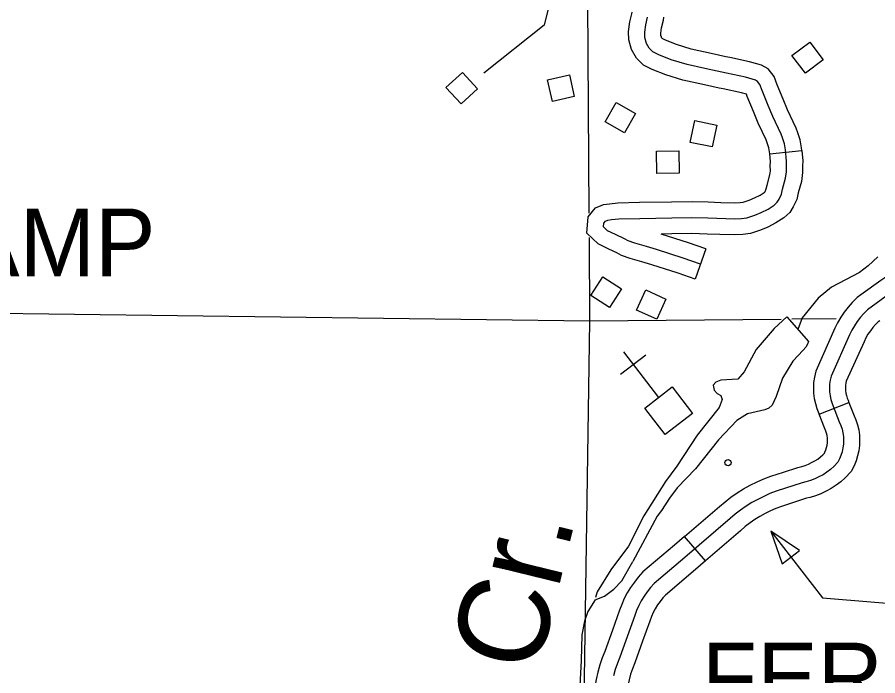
# Model space of a CAD drawing. Extents: x -19 to 366, y -4 to 359.
# Drawn here: x 137.894 to 138.656, y 192.696 to 193.279 of the extents above; entities that cross this region are included whole.
import ezdxf

# ---------------------------------------------------------------- set-up
doc = ezdxf.new("R2010")
doc.units = 0
for name, color, linetype in [('21', 7, 'Continuous'), ('60', 7, 'Continuous'), ('R_Axis Annot', 7, 'Continuous'), ('R_ROW', 7, 'Continuous'), ('R_Temp Easement', 7, 'Continuous'), ('Sheet Fence', 7, 'Continuous')]:
    doc.layers.add(name, color=color, linetype=linetype)

msp = doc.modelspace()

# ---------------------------------------------------------------- linework, layer by layer
at = {"layer": '21'}
msp.add_lwpolyline([(138.37332, 193.32549), (138.36042, 193.27203), (138.307, 193.22963)], dxfattribs=at)
for points in [[(138.60746, 193.24136), (138.59174, 193.22946), (138.57981, 193.24523), (138.59553, 193.25712)], [(138.2879, 193.23022), (138.30129, 193.21576), (138.28679, 193.20232), (138.27339, 193.21678)], [(138.36772, 193.20438), (138.36338, 193.22361), (138.38267, 193.22797), (138.38701, 193.20874)], [(138.43153, 193.17659), (138.41438, 193.18632), (138.42414, 193.20352), (138.44129, 193.19379)], [(138.48979, 193.16816), (138.49379, 193.18746), (138.51315, 193.18346), (138.50915, 193.16415)], [(138.46019, 193.14072), (138.45984, 193.16043), (138.47961, 193.16078), (138.47996, 193.14107)], [(138.41818, 193.02194), (138.4016, 193.0326), (138.4123, 193.04923), (138.42888, 193.03857)], [(138.46822, 193.02935), (138.46, 193.01144), (138.44203, 193.01969), (138.45026, 193.0376)]]:
    msp.add_lwpolyline(points, close=True, dxfattribs=at)
at = {"layer": '60'}
for p, q in [((138.43052, 192.98267), (138.46159, 192.94223)), ((138.42791, 192.96275), (138.45044, 192.98006))]:
    msp.add_line(p, q, dxfattribs=at)
for points in [[(138.5752, 193.01354), (138.59446, 192.99167)], [(138.56115, 192.82369), (138.60671, 192.76481), (138.69592, 192.75721)]]:
    msp.add_lwpolyline(points, dxfattribs=at)
for points in [[(138.46741, 192.90943), (138.4494, 192.93286), (138.4737, 192.95154), (138.49171, 192.92811)], [(138.57124, 192.79486), (138.58652, 192.80668), (138.56115, 192.82369)]]:
    msp.add_lwpolyline(points, close=True, dxfattribs=at)
msp.add_circle((138.52319, 192.88447), 0.00284, dxfattribs=at)
at = {"layer": 'R_Axis Annot'}
for points in [[(138.39812, 193.38738), (138.39994, 193.10547)], [(138.40008, 193.08395), (138.40056, 193.00992)], [(138.40056, 193.00992), (137.39691, 193.02279)], [(138.5702, 193.01139), (138.40056, 193.00992)], [(138.61903, 193.01182), (138.57979, 193.01148)], [(138.40056, 193.00992), (138.38943, 192.25821)]]:
    msp.add_lwpolyline(points, dxfattribs=at)
at = {"layer": 'R_ROW'}
for p, q in [((138.56017, 193.1581), (138.58844, 193.16089)), ((138.50342, 193.07379), (138.49407, 193.04697)), ((138.60384, 192.92728), (138.63027, 192.9377)), ((138.63027, 192.9377), (138.63027, 192.9377)), ((138.50324, 192.79746), (138.48472, 192.819))]:
    msp.add_line(p, q, dxfattribs=at)
for points in [[(138.49874, 193.06038), (138.48359, 193.06566), (138.4597, 193.07336), (138.45093, 193.07588), (138.44073, 193.07899), (138.4347, 193.08088), (138.43147, 193.08286), (138.42356, 193.08653), (138.41638, 193.08998), (138.41299, 193.09329), (138.41326, 193.09672), (138.41468, 193.09847), (138.41667, 193.09931), (138.42007, 193.09978), (138.42651, 193.10046), (138.44509, 193.1009), (138.47336, 193.10126), (138.49125, 193.10155), (138.50517, 193.10123), (138.52911, 193.10048), (138.53507, 193.10066), (138.53981, 193.10129), (138.54691, 193.10383), (138.55246, 193.10607), (138.5586, 193.10918), (138.56397, 193.11251), (138.56671, 193.11516), (138.56845, 193.1179), (138.57049, 193.12235), (138.57156, 193.12691), (138.57421, 193.13654), (138.57501, 193.14221), (138.57486, 193.14735), (138.57509, 193.15162), (138.5741, 193.16159), (138.57323, 193.16685), (138.57136, 193.17232), (138.57034, 193.17562), (138.56286, 193.19116), (138.55878, 193.20093), (138.55334, 193.21414), (138.55133, 193.2196), (138.54931, 193.2223), (138.54748, 193.22326), (138.53857, 193.22587), (138.52178, 193.22951), (138.50526, 193.23304), (138.48693, 193.23718), (138.47278, 193.24147), (138.46197, 193.24574), (138.4566, 193.24846), (138.45341, 193.25158), (138.45086, 193.25588), (138.44957, 193.26102), (138.44941, 193.26577), (138.45034, 193.2725), (138.45199, 193.27925)], [(138.5154, 193.21635), (138.50222, 193.21916), (138.4833, 193.22343), (138.4681, 193.22805), (138.45613, 193.23278), (138.44824, 193.23677), (138.44214, 193.24273), (138.43759, 193.25042), (138.43543, 193.25902), (138.43517, 193.2665), (138.43637, 193.27516), (138.43805, 193.28204), (138.43829, 193.28357)], [(138.52134, 193.24413), (138.50831, 193.24691), (138.49056, 193.25092), (138.47746, 193.25489), (138.4678, 193.25871), (138.46497, 193.26015), (138.46468, 193.26043), (138.46414, 193.26134), (138.46372, 193.26302), (138.46365, 193.26504), (138.46431, 193.26983), (138.46593, 193.27645), (138.46635, 193.27913)], [(138.58844, 193.16089), (138.58819, 193.16345), (138.58705, 193.17033), (138.58487, 193.17672), (138.5836, 193.18083), (138.57582, 193.19698), (138.5719, 193.20637), (138.56658, 193.2193), (138.56394, 193.22646), (138.55876, 193.23337), (138.55284, 193.2365), (138.54207, 193.23964), (138.52477, 193.24339), (138.52134, 193.24413)], [(138.56017, 193.1581), (138.56001, 193.15973), (138.55941, 193.16338), (138.55785, 193.16792), (138.55708, 193.17042), (138.5499, 193.18533), (138.54566, 193.19548), (138.5401, 193.20898), (138.53943, 193.21082), (138.53506, 193.21209), (138.51879, 193.21562), (138.5154, 193.21635)], [(138.58844, 193.16089), (138.58933, 193.15195), (138.58907, 193.14719), (138.58925, 193.14142), (138.58815, 193.13366), (138.58533, 193.1234), (138.58399, 193.11771), (138.58095, 193.11109), (138.57779, 193.10611), (138.57274, 193.10124), (138.56557, 193.09679), (138.55834, 193.09312), (138.55196, 193.09055), (138.54317, 193.08741), (138.53623, 193.08649), (138.5291, 193.08627), (138.51583, 193.08669)], [(138.51671, 193.11508), (138.52912, 193.1147), (138.53392, 193.11484), (138.53645, 193.11518), (138.54187, 193.11711), (138.54657, 193.11901), (138.55163, 193.12157), (138.55519, 193.12378), (138.55563, 193.1242), (138.55594, 193.1247), (138.55699, 193.12698), (138.5578, 193.13041), (138.56027, 193.13943), (138.56078, 193.143), (138.56064, 193.14752), (138.56084, 193.1513), (138.56017, 193.1581)], [(138.49407, 193.04697), (138.47907, 193.05219), (138.45556, 193.05977), (138.4469, 193.06226), (138.43652, 193.06542), (138.42878, 193.06786), (138.42475, 193.07032), (138.4175, 193.07369), (138.40813, 193.07818), (138.39829, 193.08779), (138.39946, 193.10224), (138.40587, 193.11016), (138.41084, 193.11227)], [(138.41084, 193.11227), (138.41286, 193.11312), (138.41835, 193.11388), (138.4256, 193.11464), (138.44483, 193.1151), (138.47315, 193.11546), (138.4913, 193.11576), (138.50555, 193.11543), (138.51671, 193.11508)], [(138.72716, 193.08823), (138.72171, 193.08557), (138.71338, 193.08114), (138.70516, 193.07644), (138.69711, 193.07146), (138.68943, 193.06637), (138.65842, 193.04587), (138.64091, 193.03325)], [(138.51583, 193.08669), (138.50478, 193.08703), (138.49121, 193.08734), (138.47356, 193.08705), (138.46391, 193.08693)], [(138.50342, 193.07379), (138.48811, 193.07913), (138.46391, 193.08693)], [(138.6665, 193.03418), (138.64677, 193.01996), (138.6435, 193.0167), (138.64046, 193.01323), (138.63765, 193.00957), (138.63507, 193.00573), (138.63275, 193.00174), (138.63072, 192.99759), (138.61438, 192.96098), (138.61363, 192.95758), (138.61317, 192.95412), (138.61301, 192.95064), (138.61314, 192.94716), (138.61358, 192.94369), (138.6143, 192.94028), (138.61532, 192.93695), (138.61622, 192.93461), (138.62173, 192.92062), (138.62308, 192.9175), (138.62412, 192.91426), (138.62488, 192.91095), (138.62534, 192.90758), (138.62551, 192.90419), (138.62538, 192.90079), (138.62496, 192.89743), (138.62423, 192.89411), (138.62321, 192.89088)], [(138.64091, 193.03324), (138.63754, 193.03082), (138.63314, 193.02643), (138.62947, 193.02225), (138.62611, 193.01787), (138.62302, 193.01327), (138.62021, 193.00844), (138.61785, 193.00362), (138.60082, 192.96545), (138.59964, 192.96006), (138.59901, 192.95539), (138.5988, 192.9507), (138.59897, 192.94601), (138.59956, 192.94134), (138.60053, 192.93673), (138.60188, 192.93231), (138.60298, 192.92946), (138.60384, 192.92728)], [(138.65752, 193.0102), (138.656, 193.0091), (138.65387, 193.00698), (138.65145, 193.00422), (138.6492, 193.00128), (138.64712, 192.9982), (138.64528, 192.99504), (138.64359, 192.99157), (138.62794, 192.95651), (138.62763, 192.9551), (138.62733, 192.95286), (138.62723, 192.95058), (138.62731, 192.9483), (138.6276, 192.94605), (138.62806, 192.94384), (138.62875, 192.94159), (138.62945, 192.93976), (138.63027, 192.9377)], [(138.63027, 192.9377), (138.63486, 192.92604), (138.63639, 192.9225), (138.63783, 192.91804), (138.63887, 192.9135), (138.6395, 192.9089), (138.63973, 192.90426), (138.63955, 192.89963), (138.63897, 192.89501), (138.63797, 192.89045), (138.63657, 192.886), (138.6348, 192.88176), (138.63211, 192.87655), (138.62703, 192.87103), (138.62299, 192.86748), (138.6189, 192.86439), (138.61462, 192.8616), (138.61011, 192.8591), (138.60546, 192.85694), (138.60069, 192.85511), (138.59581, 192.85363), (138.59265, 192.85288), (138.58103, 192.84907)], [(138.57218, 192.87607), (138.58494, 192.88025), (138.58841, 192.88107), (138.59146, 192.882), (138.59437, 192.88312), (138.59724, 192.88445), (138.59995, 192.88595), (138.60256, 192.88765), (138.60504, 192.88952), (138.60714, 192.89137), (138.60862, 192.89297), (138.60902, 192.89376), (138.60986, 192.89576), (138.61049, 192.89778), (138.61095, 192.89984), (138.61121, 192.90196), (138.6113, 192.90411), (138.61119, 192.90626), (138.6109, 192.9084), (138.61042, 192.91048), (138.60977, 192.91249), (138.6086, 192.91521), (138.60384, 192.92728)], [(138.62321, 192.89088), (138.62191, 192.88776), (138.62036, 192.88476), (138.61708, 192.8812), (138.61402, 192.8785), (138.61073, 192.87602), (138.60729, 192.87377), (138.60368, 192.87177), (138.59992, 192.87003), (138.59608, 192.86855), (138.59211, 192.86735), (138.58879, 192.86657), (138.56588, 192.85906), (138.56028, 192.85697), (138.55481, 192.85459), (138.54944, 192.85194), (138.5442, 192.84903), (138.53913, 192.84586), (138.53422, 192.84243), (138.5295, 192.83876), (138.52495, 192.83486), (138.48503, 192.80053), (138.4578, 192.77737), (138.45459, 192.77381), (138.4516, 192.77006), (138.44885, 192.76613), (138.44637, 192.76203), (138.44413, 192.75778), (138.44217, 192.7534), (138.44051, 192.7489), (138.42737, 192.71223), (138.42519, 192.70673), (138.42333, 192.70112), (138.42172, 192.69542)], [(138.48472, 192.819), (138.51569, 192.84563), (138.52051, 192.84977), (138.52579, 192.85387), (138.5313, 192.85771), (138.53698, 192.86126), (138.54284, 192.86453), (138.54884, 192.86749), (138.55497, 192.87014), (138.56118, 192.87247), (138.57218, 192.87607)], [(138.58103, 192.84907), (138.57058, 192.84565), (138.5656, 192.84379), (138.56078, 192.8417), (138.55604, 192.83936), (138.55143, 192.8368), (138.54697, 192.834), (138.54264, 192.83099), (138.53848, 192.82776), (138.5342, 192.82408), (138.50324, 192.79746)], [(138.48472, 192.819), (138.47579, 192.81133), (138.44788, 192.78758), (138.44375, 192.78301), (138.44021, 192.77856), (138.43694, 192.77388), (138.434, 192.76902), (138.43134, 192.76399), (138.42901, 192.75876), (138.42716, 192.75376), (138.42077, 192.73592)], [(138.50324, 192.79746), (138.49426, 192.78974), (138.46771, 192.76716), (138.46543, 192.76462), (138.46299, 192.76156), (138.46076, 192.75837), (138.45874, 192.75503), (138.45691, 192.75157), (138.45533, 192.74803), (138.45386, 192.74404), (138.44752, 192.72634)], [(138.42077, 192.73592), (138.41408, 192.71724), (138.41184, 192.71159), (138.40974, 192.70529), (138.40794, 192.69891), (138.40649, 192.69242), (138.40535, 192.68588), (138.40457, 192.67929), (138.4041, 192.67265), (138.40401, 192.66603), (138.40421, 192.65945), (138.40456, 192.65504), (138.40741, 192.63198)], [(138.44752, 192.72634), (138.44067, 192.70722), (138.43855, 192.70186), (138.43691, 192.69695), (138.4355, 192.69194), (138.43436, 192.68688), (138.43348, 192.68177), (138.43286, 192.67661), (138.4325, 192.67145), (138.43242, 192.66625), (138.43258, 192.66101), (138.43283, 192.65793), (138.43561, 192.63547)]]:
    msp.add_lwpolyline(points, dxfattribs=at)
at = {"layer": 'R_Temp Easement'}
for points in [[(138.6558, 193.06691), (138.64722, 193.0587), (138.6396, 193.05305), (138.6147, 193.03991), (138.60297, 193.03019), (138.58873, 193.01289), (138.58503, 193.00237)], [(138.5752, 193.01354), (138.5639, 193.00325), (138.5481, 192.9846), (138.5376, 192.96484), (138.53195, 192.95837), (138.51683, 192.95755), (138.5123, 192.95564), (138.51005, 192.95297), (138.51082, 192.9488), (138.51348, 192.94578), (138.51689, 192.94389), (138.51804, 192.94048), (138.51542, 192.93326), (138.49586, 192.90891), (138.47793, 192.88145)], [(138.59446, 192.99167), (138.59346, 192.98933), (138.59195, 192.98667), (138.58967, 192.98398), (138.58066, 192.97449), (138.57127, 192.95927), (138.56567, 192.94294), (138.5623, 192.93534), (138.55929, 192.93267), (138.55589, 192.93114), (138.5404, 192.92767), (138.53097, 192.92194), (138.51479, 192.90481), (138.49448, 192.87893), (138.47806, 192.86224)], [(138.47793, 192.88145), (138.4678, 192.86765), (138.44862, 192.8372), (138.43498, 192.8105)], [(138.47806, 192.86224), (138.47129, 192.85292), (138.46428, 192.84209), (138.46043, 192.83692), (138.43901, 192.79683)], [(138.43498, 192.8105), (138.41948, 192.78942), (138.40744, 192.77011), (138.40574, 192.76485)], [(138.4055, 192.76294), (138.41381, 192.76601), (138.4221, 192.77249), (138.42925, 192.77972), (138.43901, 192.79683)], [(138.4055, 192.76294), (138.39902, 192.75266), (138.39603, 192.74393), (138.39381, 192.73178), (138.39315, 192.70901), (138.3914, 192.67562)]]:
    msp.add_lwpolyline(points, dxfattribs=at)
at = {"layer": 'Sheet Fence'}
for points in [[(146.77834, 1.69699), (146.57878, 10.31313), (146.37852, 18.92942), (146.17757, 27.54584), (145.97591, 36.16241), (145.77356, 44.77911), (145.57052, 53.39596), (145.36679, 62.01295), (145.16236, 70.63008), (144.95724, 79.24735), (144.75142, 87.86477), (144.54492, 96.48232), (144.33773, 105.10002), (144.12986, 113.71787), (143.92129, 122.33585), (143.71204, 130.95398), (143.5021, 139.57225), (143.29148, 148.19067), (143.08018, 156.80923), (142.8682, 165.42794), (142.65553, 174.04679), (142.44218, 182.66579), (142.22816, 191.28493), (142.01345, 199.90421), (141.79807, 208.52365), (141.58202, 217.14322), (141.36528, 225.76295), (141.14788, 234.38282), (140.9298, 243.00284), (140.71105, 251.623), (140.49162, 260.24332), (140.27153, 268.86377), (140.05077, 277.48438), (139.82934, 286.10514), (139.60724, 294.72604), (139.38447, 303.34709), (139.16105, 311.96829), (138.93695, 320.58964), (138.7122, 329.21114), (138.48678, 337.83278), (138.2607, 346.45458)], [(139.44064, 1.53154), (139.25106, 10.14733), (139.06082, 18.76327), (138.86992, 27.37935), (138.67836, 35.99557), (138.48613, 44.61194), (138.29325, 53.22845), (138.09971, 61.84511), (137.9055, 70.46191), (137.71065, 79.07885), (137.51513, 87.69595), (137.31896, 96.31318), (137.12214, 104.93057), (136.92466, 113.54809), (136.72653, 122.16577), (136.52775, 130.78359), (136.32832, 139.40156), (136.12824, 148.01968), (135.9275, 156.63794), (135.72612, 165.25636), (135.5241, 173.87492), (135.32143, 182.49362), (135.11811, 191.11248), (134.91415, 199.73149), (134.70954, 208.35064), (134.50429, 216.96995), (134.2984, 225.5894), (134.09187, 234.209), (133.8847, 242.82876), (133.6769, 251.44866), (133.46845, 260.06872), (133.25937, 268.68892), (133.04965, 277.30928), (132.8393, 285.92978), (132.62831, 294.55044), (132.41669, 303.17125), (132.20444, 311.79221), (131.99156, 320.41333), (131.77805, 329.0346), (131.56391, 337.65601), (131.34914, 346.27759)], [(0, 189.51617), (7.11214, 189.52059), (14.22427, 189.53386), (21.33637, 189.55597), (28.44845, 189.58693), (35.56048, 189.62672), (42.67245, 189.67537), (49.78436, 189.73285), (56.89619, 189.79918), (64.00793, 189.87436), (71.11958, 189.95838), (78.23111, 190.05124), (85.34253, 190.15294), (92.45381, 190.26349), (99.56495, 190.38288), (106.67593, 190.51112), (113.78675, 190.6482), (120.89739, 190.79412), (128.00785, 190.94888), (135.11811, 191.11248), (142.22816, 191.28493), (149.33799, 191.46621), (156.44759, 191.65634), (163.55694, 191.85531), (170.66605, 192.06312), (177.77489, 192.27977), (184.88345, 192.50526), (191.99173, 192.73959), (199.09971, 192.98276), (206.20739, 193.23477), (213.31474, 193.49561), (220.42177, 193.7653), (227.52845, 194.04382), (234.63479, 194.33118), (241.74076, 194.62738), (248.84635, 194.93241), (255.95157, 195.24628), (263.05638, 195.56898), (270.16079, 195.90052), (277.26478, 196.24089), (284.36834, 196.5901), (291.47147, 196.94814), (298.57414, 197.31501), (305.67635, 197.69072), (312.77809, 198.07525), (319.87934, 198.46862), (326.9801, 198.87082), (334.08035, 199.28185), (341.18009, 199.7017)]]:
    msp.add_spline(points, degree=3, dxfattribs=at)

# ---------------------------------------------------------------- texts
at = {"layer": '60'}
for s, p in [('BAPTIST CAMP', (137.4277, 193.04961)), ('FERNCLIFF', (138.49993, 192.66491))]:
    msp.add_text(s, height=0.06, dxfattribs=at).set_placement(p)
at = {"layer": 'R_Temp Easement'}
msp.add_text('Cr.', height=0.08, rotation=76.24136, dxfattribs=at).set_placement((138.35417, 192.69565))

doc.saveas('drawing.dxf')
